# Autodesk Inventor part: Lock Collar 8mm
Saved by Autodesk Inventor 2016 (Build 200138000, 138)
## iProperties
Created: 2016-03
Part Number: Lock Collar 8mm
Material: Generic
Document SubType Name: Modeling
Designer: bongo_000
Density: 1 g/cm^3
Appearance: Default
Author: bongo_000
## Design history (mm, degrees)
feature "M5X0.8 TAPPED HOLE1"
body "Solid1"
